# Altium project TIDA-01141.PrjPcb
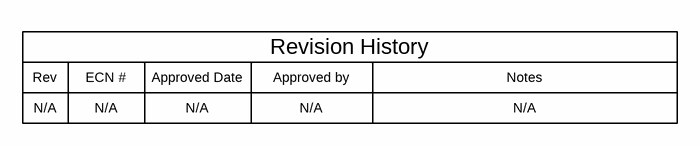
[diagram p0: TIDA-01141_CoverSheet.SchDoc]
CopyrightYear: 2016; EVM_Orderable: N/A; PCB_Layout: Akshay Labhe; PCB_Rev: E1; PRJ_Customer: Public Release; PRJ_Engineer: Ramkumar S; PRJ_Number: TIDA-01141; PRJ_Title: Current Sensing Solution; SCH_Rev: E1; TechSupport: http://www.ti.com/support; TID: TIDA-01141
3 sheets, 34 parts. Net scope: global (net labels, ports and power ports of the same name join across sheets).
Board file: TIDA-01141.PcbDoc
Sheets:
  TIDA-01141_CoverSheet.SchDoc
  TIDA-01141_Sheet1.SchDoc
  TIDA-01141_Hardware.SchDoc

## Sheet TIDA-01141_CoverSheet.SchDoc
size 431 x 279 mm; Date: Not shown in title block; ApprovedBy: Not shown in title block; CheckedBy: Not shown in title block; Author: Not shown in title block; CompanyName: Not shown in title block; DrawnBy: Ramkumar S; Engineer: Not shown in title block; Organization: Not shown in title block; Address1: Not shown in title block; Address2: Not shown in title block; Address3: Not shown in title block; Address4: Not shown in title block; DocumentNumber: 1; Revision: Use project parameter SCH_Rev; SheetNumber: 1; SheetTotal: 3; PageSetup: Record=PageOptions¦CenterHorizontal=True¦CenterVertical=True¦PrintScale=1.00¦XCorrection=1.00¦YCorrection=1.00¦PrintKind=0¦BorderSize=5000000¦LeftOffset=0¦BottomOffset=0¦Orientation=2¦PaperLength=1000¦PaperWidth=1000¦Scale=100¦PaperSource=15¦PrintQuality=600¦MediaType=1¦DitherType=10¦PaperKind=Letter¦PrintScaleMode=1

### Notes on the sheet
- Rev
- N/A
- ECN #
- Approved Date
- Approved by
- Revision History
- Notes

## Sheet TIDA-01141_Sheet1.SchDoc
size 431 x 279 mm; Date: Not shown in title block; ApprovedBy: Not shown in title block; CheckedBy: Not shown in title block; Author: Not shown in title block; CompanyName: Not shown in title block; DrawnBy: Ramkumar S; Engineer: Not shown in title block; Organization: Not shown in title block; Address1: Not shown in title block; Address2: Not shown in title block; Address3: Not shown in title block; Address4: Not shown in title block; DocumentNumber: 1; Revision: Use project parameter SCH_Rev; SheetNumber: 2; SheetTotal: 3; PageSetup: Record=PageOptions¦CenterHorizontal=True¦CenterVertical=True¦PrintScale=1.00¦XCorrection=1.00¦YCorrection=1.00¦PrintKind=0¦BorderSize=5000000¦LeftOffset=0¦BottomOffset=0¦Orientation=2¦PaperLength=1000¦PaperWidth=1000¦Scale=100¦PaperSource=15¦PrintQuality=600¦MediaType=1¦DitherType=10¦PaperKind=Letter¦PrintScaleMode=1
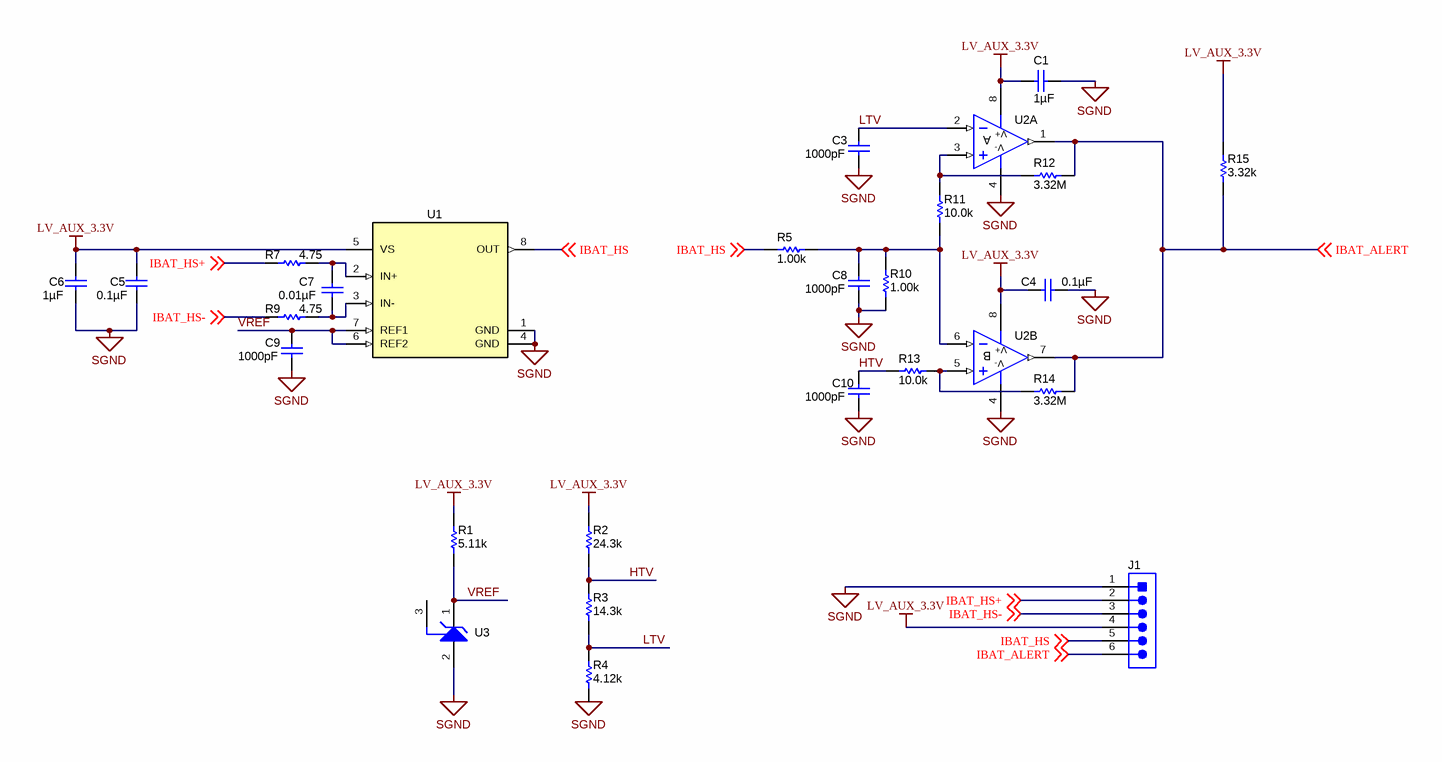
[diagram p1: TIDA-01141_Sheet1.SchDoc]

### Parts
C1  ValueDisplayed: 1µF  [0603]  (hidden comment: C0603C105K8PACTU)
C3  ValueDisplayed: 1000pF  [0603]  (hidden comment: 06031C102JAT2A)
C4  ValueDisplayed: 0.1µF  [0603]  (hidden comment: GRM188R71C104KA01D)
C5  ValueDisplayed: 0.1µF  [0603]  (hidden comment: GRM188R71C104KA01D)
C6  ValueDisplayed: 1µF  [0603]  (hidden comment: C0603C105K8PACTU)
C7  ValueDisplayed: 0.01µF  [0603]  (hidden comment: 06031C103JAT2A)
C8  ValueDisplayed: 1000pF  [0603]  (hidden comment: 06031C102JAT2A)
C9  ValueDisplayed: 1000pF  [0603]  (hidden comment: 06031C102JAT2A)
C10  ValueDisplayed: 1000pF  [0603]  (hidden comment: 06031C102JAT2A)
J1  TSW-106-08-G-S-RA  [TSW-106-08-G-S-RA]  (value not drawn)
R1  ValueDisplayed: 5.11k  [0603]  (hidden comment: RC0603FR-075K11L)
R2  ValueDisplayed: 24.3k  [0603]  (hidden comment: CRCW060324K3FKEA)
R3  ValueDisplayed: 14.3k  [0603]  (hidden comment: CRCW060314K3FKEA)
R4  ValueDisplayed: 4.12k  [0603]  (hidden comment: CRCW06034K12FKEA)
R5  ValueDisplayed: 1.00k  [0805_HV1]  (hidden comment: CRCW08051K00FKEA)
R7  ValueDisplayed: 4.75  [0603]  (hidden comment: CRCW06034R75FKEA)
R9  ValueDisplayed: 4.75  [0603]  (hidden comment: CRCW06034R75FKEA)
R10  ValueDisplayed: 1.00k  [0603]  (hidden comment: CRCW06031K00FKEA)
R11  ValueDisplayed: 10.0k  [0603]  (hidden comment: CRCW060310K0FKEA)
R12  ValueDisplayed: 3.32M  [0603]  (hidden comment: CRCW06033M32FKEA)
R13  ValueDisplayed: 10.0k  [0603]  (hidden comment: CRCW060310K0FKEA)
R14  ValueDisplayed: 3.32M  [0603]  (hidden comment: CRCW06033M32FKEA)
R15  ValueDisplayed: 3.32k  [0603]  (hidden comment: CRCW06033K32FKEA)
U1  INA240A2PW  [PW0008A_N]  (value not drawn)
U2  LM393AD  [D0008A_N]  (value not drawn)  (parts A,B of 2)
U3  LM4040D30IDBZR  [DBZ0003A_N]  (value not drawn)

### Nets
LV_AUX_3.3V: C1.2 C4.1 C5.1 C6.2 J1.4 R1.2 R2.2 R15.2 U1.5(VS) U2.8(V+)
SGND: C1.1 C3.1 C4.2 C5.2 C6.1 C8.1 C9.1 C10.1 J1.1 R4.1 R10.2 U1.1(GND) U1.4(GND) U2.4(V-) U3.2(ANODE)
HTV: C10.2 R2.1 R3.2 R13.2
IBAT_ALERT: J1.6 R12.2 R14.2 R15.1 U2.1(OUT) U2.7(OUT) ; off-sheet IBAT_ALERT
IBAT_HS: J1.5 R5.1 U1.8(OUT) ; off-sheet IBAT_HS
IBAT_HS+: J1.2 R7.1 ; off-sheet IBAT_HS+
IBAT_HS-: J1.3 R9.1 ; off-sheet IBAT_HS-
LTV: C3.2 R3.1 R4.2 U2.2(IN-)
VREF: C9.2 R1.1 U1.6(REF2) U1.7(REF1) U3.1(CATHODE)
NetC7_1: C7.1 R7.2 U1.2(IN+)
NetC7_2: C7.2 R9.2 U1.3(IN-)
NetC8_2: C8.2 R5.2 R10.1 R11.1 U2.6(IN-)
NetR11_2: R11.2 R12.1 U2.3(IN+)
NetR13_1: R13.1 R14.1 U2.5(IN+)

Not connected (* = marked no-connect by the designer): U3 3(NC)

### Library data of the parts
C1 C6 = C0603C105K8PACTU: CAP, CERM, 1 µF, 10 V, +/- 10%, X5R, 0603; Manufacturer: Kemet; Polarized: N; CompType: Capacitor; Value: 1uF; U/M: EA; Cap_F: 0.000001; Tolerance_%: 10; Value1: Unknown; Value2: 10V; TaMin_C: -55; TaMax_C: 85
C3 C8-C10 = 06031C102JAT2A: CAP, CERM, 1000 pF, 100 V, +/- 5%, X7R, 0603; Manufacturer: AVX; Polarized: N; CompType: Capacitor; Value: 1000pF; U/M: EA; Cap_F: 0.000000001; Tolerance_%: 5; ESR_ohm: 0.276; Value1: 0.276 ohm; VDC_V: 100; Value2: 100V; TaMin_C: -55; TaMax_C: 125; SizeArea_mm2: 1.28; SizeAreaWB_mm2: 4.68; SizeX_mm: 1.6; SizeY_mm: 0.8; SizeZ_mm: 1; AEC Category: Q200
C4 C5 = GRM188R71C104KA01D: CAP, CERM, 0.1 µF, 16 V, +/- 10%, X7R, 0603; Manufacturer: MuRata; Polarized: N; CompType: Capacitor; Value: 0.1uF; U/M: EA; Cap_F: 0.0000001; Tolerance_%: 10; Value1: Unknown; VDC_V: 16; Value2: 16V; TaMin_C: -55; TaMax_C: 125; SizeArea_mm2: 1.28; SizeAreaWB_mm2: 4.68; SizeX_mm: 1.6; SizeY_mm: 0.8; SizeZ_mm: 1; AEC Category: Q200
C7 = 06031C103JAT2A: CAP, CERM, 0.01 µF, 100 V, +/- 5%, X7R, 0603; Manufacturer: AVX; Polarized: N; CompType: Capacitor; Value: 0.01uF; U/M: EA; Cap_F: 0.00000001; Tolerance_%: 5; ESR_ohm: 0.098; Value1: 0.098 ohm; VDC_V: 100; Value2: 100V; TaMin_C: -55; TaMax_C: 125
J1 = TSW-106-08-G-S-RA: Header, 100mil, 6x1, Gold, R/A, TH; Manufacturer: Samtec; SymbolCreator: a0412235; Pitch_mm: 2.54; Gender: Male; Shrouded: N; Row_Count: 1; Current_A: 6.3; Voltage_V: 550; Cert_CSA: Y
R1 = RC0603FR-075K11L: RES, 5.11 k, 1%, 0.1 W, 0603; Manufacturer: Yageo America; CompType: Resistor; Value: 5.11k; Res_ohm: 5110; Value_Code: 5k11; Tolerance_%: 1; Power_W: 0.1; Value2: 0.1W; VDC_V: 150; TempCo: 200 ppm/C; EIA_Code: E96; U/M: EA
R2 = CRCW060324K3FKEA: RES, 24.3 k, 1%, 0.1 W, 0603; Manufacturer: Vishay-Dale; CompType: Resistor; Value: 24.3k; Res_ohm: 24300; Value_Code: 24k3; Tolerance_%: 1; Power_W: 0.1; Value2: 0.1W; VDC_V: 75; TempCo: 100 ppm/C; EIA_Code: E96; U/M: EA
R3 = CRCW060314K3FKEA: RES, 14.3 k, 1%, 0.1 W, 0603; Manufacturer: Vishay-Dale; CompType: Resistor; Value: 14.3k; Res_ohm: 14300; Value_Code: 14k3; Tolerance_%: 1; Power_W: 0.1; Value2: 0.1W; VDC_V: 75; TempCo: 100 ppm/C; EIA_Code: E96; U/M: EA
R4 = CRCW06034K12FKEA: RES, 4.12 k, 1%, 0.1 W, 0603; Manufacturer: Vishay-Dale; CompType: Resistor; Value: 4.12k; Res_ohm: 4120; Value_Code: 4k12; Tolerance_%: 1; Power_W: 0.1; Value2: 0.1W; VDC_V: 75; TempCo: 100 ppm/C; EIA_Code: E96; U/M: EA
R5 = CRCW08051K00FKEA: RES, 1.00 k, 1%, 0.125 W, 0805; Manufacturer: Vishay-Dale; CompType: Resistor; Value: 1.00k; Res_ohm: 1000; Value_Code: 1k00; Tolerance_%: 1; Power_W: 0.125; Value2: 0.125W; VDC_V: 150; TempCo: 100 ppm/C; EIA_Code: E96; U/M: EA; AEC Category: Q200
R7 R9 = CRCW06034R75FKEA: RES, 4.75, 1%, 0.1 W, 0603; Manufacturer: Vishay-Dale; CompType: Resistor; Value: 4.75; Value_Code: 4R75; Tolerance_%: 1; Power_W: 0.1; Value2: 0.1W; VDC_V: 75; TempCo: 100 ppm/C; EIA_Code: E96; U/M: EA
R10 = CRCW06031K00FKEA: RES, 1.00 k, 1%, 0.1 W, 0603; Manufacturer: Vishay-Dale; CompType: Resistor; Value: 1.00k; Res_ohm: 1000; Value_Code: 1k00; Tolerance_%: 1; Power_W: 0.1; Value2: 0.1W; VDC_V: 75; TempCo: 100 ppm/C; SizeArea_mm2: 1.28; SizeX_mm: 1.6; SizeY_mm: 0.8; EIA_Code: E96; U/M: EA; AEC Category: Q200
R11 R13 = CRCW060310K0FKEA: RES, 10.0 k, 1%, 0.1 W, 0603; Manufacturer: Vishay-Dale; CompType: Resistor; Value: 10.0k; Res_ohm: 10000; Value_Code: 10k0; Tolerance_%: 1; Power_W: 0.1; Value2: 0.1W; VDC_V: 75; TempCo: 100 ppm/C; EIA_Code: E96; U/M: EA
R12 R14 = CRCW06033M32FKEA: RES, 3.32 M, 1%, 0.1 W, 0603; Manufacturer: Vishay-Dale; CompType: Resistor; Value: 3.32Meg; Res_ohm: 3320000; Value_Code: 3M32; Tolerance_%: 1; Power_W: 0.1; Value2: 0.1W; VDC_V: 75; TempCo: 100 ppm/C; EIA_Code: E96; U/M: EA
R15 = CRCW06033K32FKEA: RES, 3.32 k, 1%, 0.1 W, 0603; Manufacturer: Vishay-Dale; CompType: Resistor; Value: 3.32k; Res_ohm: 3320; Value_Code: 3k32; Tolerance_%: 1; Power_W: 0.1; Value2: 0.1W; VDC_V: 75; TempCo: 100 ppm/C; EIA_Code: E96; U/M: EA
U1 = INA240A2PW: Wide Common-Mode Range, Voltage Output, High or Low-Side Bi-Directional Zero-Drift Current Shunt Monitor, PW0008A; Manufacturer: Texas Instruments; SymbolCreator: Altium; SizeArea_mm2: 19.2; SizeAreaWB_mm2: 42; SizeX_mm: 6.4; SizeY_mm: 3; SizeZ_mm: 1.2; CompType: IC; U/M: EA
U2 = LM393AD: Dual Comparator, D0008A; Manufacturer: Texas Instruments; CompType: OpAmp IC
U3 = LM4040D30IDBZR: Precision Micropower Shunt Voltage Reference, 1% accuracy, 3 V, 15 ppm / degC, 15 mA, -40 to 85 degC, 3-pin SOT-23 (DBZ), Green (RoHS & no Sb/Br); Manufacturer: Texas Instruments; Alternate PartNumber: Equivalent; Initial Accuracy @ 25/deg C(%): 1; Iout/Iz(Max)(mA): 15; Min Iz for Regulation(uA): 65; Rating: Catalog; Temp Coeff(Max)(ppm/ degree C): 150; VO(V): 3

## Sheet TIDA-01141_Hardware.SchDoc
size 431 x 279 mm; Date: Not shown in title block; ApprovedBy: Not shown in title block; CheckedBy: Not shown in title block; Author: Not shown in title block; CompanyName: Not shown in title block; Engineer: Not shown in title block; Organization: Not shown in title block; Address1: Not shown in title block; Address2: Not shown in title block; Address3: Not shown in title block; Address4: Not shown in title block; DocumentNumber: 1; Revision: Use project parameter SCH_Rev; SheetNumber: 3; SheetTotal: 3; PageSetup: Record=PageOptions¦CenterHorizontal=True¦CenterVertical=True¦PrintScale=1.00¦XCorrection=1.00¦YCorrection=1.00¦PrintKind=0¦BorderSize=5000000¦LeftOffset=0¦BottomOffset=0¦Orientation=2¦PaperLength=1000¦PaperWidth=1000¦Scale=100¦PaperSource=15¦PrintQuality=600¦MediaType=1¦DitherType=10¦PaperKind=Letter¦PrintScaleMode=1
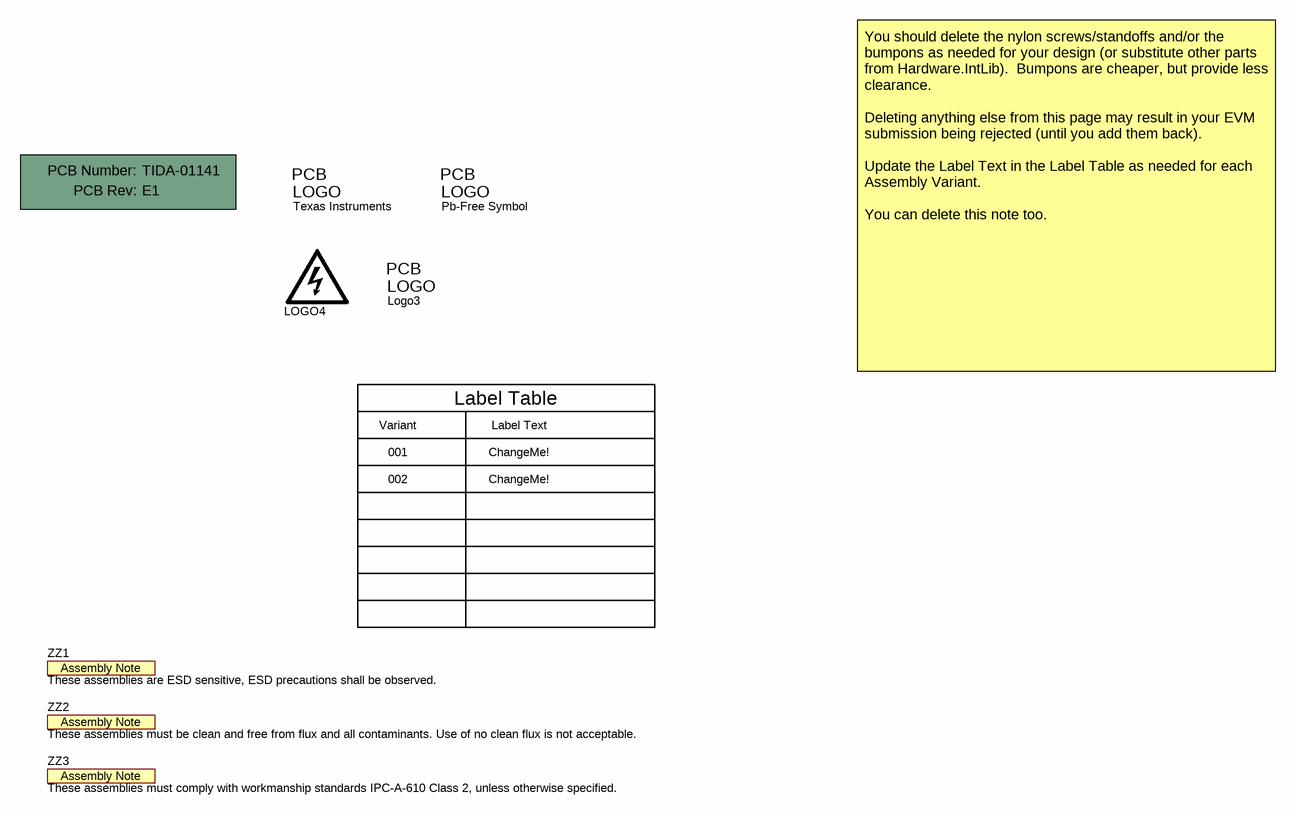
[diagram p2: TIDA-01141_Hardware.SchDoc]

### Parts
!PCB1  Printed Circuit Board  (value not drawn)  (mechanical)
Logo1  Texas Instruments  [TI_Symbol_Overlay_Small]  (no BOM)
Logo2  Pb-Free Symbol  [Pb-Free_Overlay_Small]  (no BOM)
Logo3  ESD Susceptible  [ESD_Overlay_Small]  (value not drawn)  (no BOM)
LOGO4  DANGER HIGH VOLTAGE  [IEC_HighVoltage_Small]  (value not drawn)  (no BOM)
ZZ1  These assemblies are ESD sensitive, ESD precautions shall be observed.  [AssemblyNote]  (no BOM)
ZZ2  These assemblies must be clean and free from flux and all contaminants. Use of no clean flux is not acceptable.  [AssemblyNote]  (no BOM)
ZZ3  These assemblies must comply with workmanship standards IPC-A-610 Class 2, unless otherwise specified.  [AssemblyNote]  (no BOM)

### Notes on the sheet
- Variant
- Label Table
- Label Text
- You should delete the nylon screws/standoffs and/or the bumpons as needed for your design (or substitute other parts from Hardware.IntLib).  Bumpons are cheaper, but provide less clearance.
  Deleting anything else from this page may result in your EVM submission being rejected (until you add them back).
  Update the Label Text in the Label Table as needed for each Assembly Variant.
  You can delete this note too.
- 001
- 002
- ChangeMe!

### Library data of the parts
!PCB1 = PCB: Manufacturer: Any; PartNumber: TIDA-01141; SymbolCreator: a0412235
Logo1 = TI_Logo: Texas Instrument Corporate Signature; SymbolCreator: codlsc
Logo2 = Pb-Free: SymbolCreator: a0412235
Logo3 = ESD_Susceptible: ESD Susceptible Symbol; SymbolCreator: a0412235
LOGO4 = IEC_HighVoltage: IEC 61010-1 High Voltage Warning; SymbolCreator: a0412235
ZZ1-ZZ3 = AssemblyNote: SymbolCreator: codlsc

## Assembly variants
001: not fitted FID1 FID2 FID3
